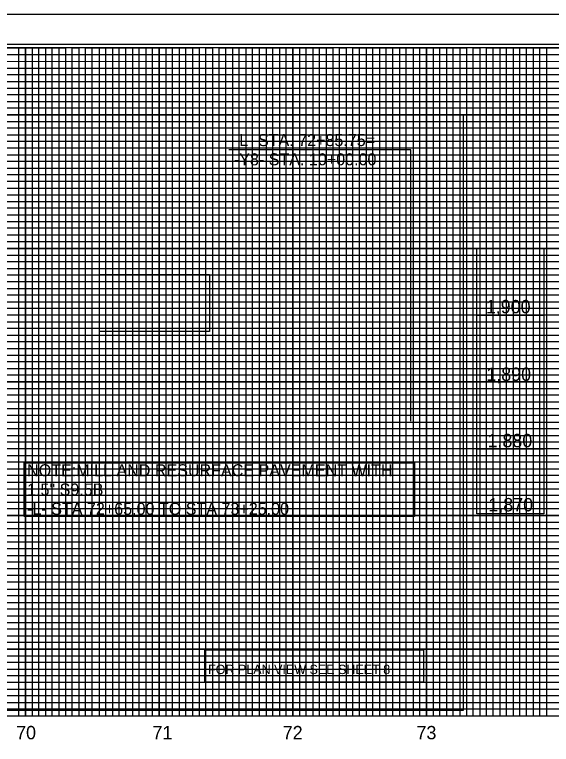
# Model space of a CAD drawing. Extents: x 557032 to 558840, y 515971 to 517218.
# Drawn here: x 557641 to 558043, y 516672 to 517218 of the extents above; entities that cross this region are included whole.
import ezdxf

# ---------------------------------------------------------------- set-up
doc = ezdxf.new("R2010")
doc.units = 0
for name, color, linetype in [('Exist Vertical Profile Horizontal Axis Label Major', 7, 'Continuous'), ('Exist Vertical Profile Vertical Axis Label', 7, 'Continuous'), ('Prop Dimension', 7, 'Continuous'), ('Prop Vertical Profile Grade Label', 7, 'Continuous'), ('Prop VPI Label', 7, 'Continuous'), ('Scratch_Level_5', 7, 'Continuous'), ('Sheet Cutting Line CELL', 7, 'Continuous'), ('Sheet DOT Grid CELL', 7, 'Continuous'), ('Sheet Layout Profile Border Port 1', 7, 'Continuous'), ('Sheet Plot Border Inside CELL', 7, 'Continuous'), ('Sheet Plot Border Outside CELL', 7, 'Continuous'), ('Sheet Profile CELL', 7, 'Continuous'), ('Sheet Profile Grid Major CELL', 7, 'Continuous'), ('Sheet Profile Grid Middle CELL', 7, 'Continuous'), ('Sheet Profile Grid Minor CELL', 7, 'Continuous')]:
    doc.layers.add(name, color=color, linetype=linetype)

msp = doc.modelspace()

# ---------------------------------------------------------------- linework, layer by layer
at = {"layer": 'Prop Dimension'}
msp.add_lwpolyline([(557987.25, 517043.03), (558037.25, 517043.03), (558037.25, 516844.53), (557987.25, 516844.53)], close=True, dxfattribs=at)
at = {"layer": 'Prop Vertical Profile Grade Label'}
msp.add_lwpolyline([(557704.75, 517023.61), (557787.24, 517023.61), (557787.24, 516980.88), (557704.75, 516980.88)], close=True, dxfattribs=at)
at = {"layer": 'Prop VPI Label'}
for p, q in [((557937.8, 517116.93), (557801.7, 517116.93)), ((557937.8, 516913.82), (557937.8, 517116.93))]:
    msp.add_line(p, q, dxfattribs=at)
for points in [[(557648.49, 516883.17), (557940.55, 516883.17), (557940.55, 516842.35), (557648.49, 516842.35)], [(557648.9, 516882.67), (557939.86, 516882.67), (557939.86, 516842.66), (557648.9, 516842.66)], [(557783.58, 516742.65), (557947.28, 516742.65), (557947.28, 516718.54), (557783.58, 516718.54)], [(557783.58, 516742.65), (557947.28, 516742.65), (557947.28, 516718.54), (557783.58, 516718.54)]]:
    msp.add_lwpolyline(points, close=True, dxfattribs=at)
at = {"layer": 'Scratch_Level_5'}
msp.add_lwpolyline([(557249.45, 516896.35), (557249.45, 517017.65), (557251.99, 517143.31), (557976.89, 517143.33), (557976.9, 516697.32), (557249.46, 516697.3)], close=True, dxfattribs=at)
at = {"layer": 'Sheet Cutting Line CELL'}
msp.add_line((558716.45, 517218.17), (557032.45, 517218.17), dxfattribs=at)
at = {"layer": 'Sheet DOT Grid CELL'}
for p, q in [((557649.45, 516693.17), (557649.45, 517193.17)), ((557699.45, 516693.17), (557699.45, 517193.17)), ((557749.45, 516693.17), (557749.45, 517193.17)), ((557799.45, 516693.17), (557799.45, 517193.17)), ((557849.45, 516693.17), (557849.45, 517193.17)), ((557899.45, 516693.17), (557899.45, 517193.17)), ((557949.45, 516693.17), (557949.45, 517193.17)), ((557999.45, 516693.17), (557999.45, 517193.17)), ((558499.4, 517143.17), (557199.45, 517143.17)), ((558499.4, 517093.17), (557199.45, 517093.17)), ((558499.45, 517043.17), (557199.45, 517043.17)), ((558699.45, 516993.17), (557199.45, 516993.17)), ((558699.45, 516943.17), (557199.45, 516943.17)), ((558699.45, 516893.17), (557199.45, 516893.17)), ((558699.45, 516843.17), (557199.45, 516843.17)), ((558699.45, 516793.17), (557199.45, 516793.17)), ((558699.45, 516743.17), (557199.45, 516743.17))]:
    msp.add_line(p, q, dxfattribs=at)
at = {"layer": 'Sheet Layout Profile Border Port 1'}
msp.add_lwpolyline([(557249.45, 517032.12), (557249.45, 516693.17), (558649.45, 516693.17), (558649.45, 517032.12)], dxfattribs=at)
at = {"layer": 'Sheet Plot Border Inside CELL'}
msp.add_lwpolyline([(557045.45, 516140.62), (558711.95, 516140.62), (558711.95, 517195.72), (557045.45, 517195.72)], close=True, dxfattribs=at)
at = {"layer": 'Sheet Plot Border Outside CELL'}
msp.add_lwpolyline([(557032.45, 516118.17), (558716.45, 516118.17), (558716.45, 517218.17), (557032.45, 517218.17)], close=True, dxfattribs=at)
at = {"layer": 'Sheet Profile CELL'}
msp.add_line((557199.45, 516693.17), (558699.45, 516693.17), dxfattribs=at)
msp.add_lwpolyline([(558699.45, 517193.17), (557199.45, 517193.17), (557199.45, 516143.17), (558699.45, 516143.17)], close=True, dxfattribs=at)
at = {"layer": 'Sheet Profile Grid Major CELL'}
for p, q in [((557949.45, 517043.17), (557949.45, 516844.8)), ((557999.45, 516993.17), (557924.45, 516993.17)), ((557987.25, 516993.17), (558037.25, 516993.17)), ((557999.45, 516943.17), (557924.45, 516943.17)), ((557987.25, 516943.17), (558037.25, 516943.17)), ((557999.45, 516893.17), (557924.45, 516893.17)), ((557987.25, 516893.17), (558037.25, 516893.17))]:
    msp.add_line(p, q, dxfattribs=at)
for points in [[(557599.45, 517193.17), (557649.45, 517193.17), (557649.45, 516693.17), (557699.45, 516693.17), (557699.45, 517193.17), (557749.45, 517193.17), (557749.45, 516693.17), (557799.45, 516693.17), (557799.45, 517193.17), (557849.45, 517193.17), (557849.45, 516693.17), (557899.45, 516693.17), (557899.45, 517193.17), (557949.45, 517193.17), (557949.45, 516693.17), (557999.45, 516693.17), (557999.45, 517193.17), (558049.45, 517193.17)], [(557199.45, 517143.17), (558499.45, 517143.17)], [(558499.45, 517093.17), (557199.45, 517093.17), (557199.45, 517043.17), (558499.45, 517043.17)], [(558699.45, 516993.17), (557199.45, 516993.17), (557199.45, 516943.17), (558699.45, 516943.17)], [(558699.45, 516893.17), (557199.45, 516893.17), (557199.45, 516843.17), (558699.45, 516843.17)], [(558699.45, 516793.17), (557199.45, 516793.17), (557199.45, 516793.17), (557199.45, 516743.17), (558699.45, 516743.17)]]:
    msp.add_lwpolyline(points, dxfattribs=at)
at = {"layer": 'Sheet Profile Grid Middle CELL'}
msp.add_line((557199.45, 517168.17), (558499.4, 517168.17), dxfattribs=at)
for points in [[(557624.45, 517193.17), (557674.45, 517193.17), (557674.45, 516693.17), (557724.45, 516693.17), (557724.45, 517193.17), (557774.45, 517193.17), (557774.45, 516693.17), (557824.45, 516693.17), (557824.45, 516693.17), (557824.45, 517193.17), (557874.45, 517193.17), (557874.45, 516693.17), (557924.45, 516693.17), (557924.45, 517193.17), (557974.45, 517193.17), (557974.45, 516693.17), (558024.45, 516693.17), (558024.45, 517193.17), (558074.45, 517193.17)], [(558499.45, 517118.17), (557199.45, 517118.17), (557199.45, 517068.17), (558499.45, 517068.17)], [(558699.45, 517018.17), (557199.45, 517018.17), (557199.45, 516968.17), (558524.45, 516968.17)], [(558699.45, 516918.17), (557199.45, 516918.17), (557199.45, 516868.17), (558699.45, 516868.17)], [(558699.45, 516818.17), (557199.45, 516818.17), (557199.45, 516768.17), (558699.45, 516768.17)], [(558699.45, 516718.17), (557199.45, 516718.17)]]:
    msp.add_lwpolyline(points, dxfattribs=at)
at = {"layer": 'Sheet Profile Grid Minor CELL'}
for p, q in [((557249.45, 517188.17), (558499.45, 517188.17)), ((558499.45, 517183.17), (557249.45, 517182.82)), ((557249.45, 517178.17), (558499.45, 517178.17)), ((558499.4, 517058.17), (557249.45, 517058.17)), ((558499.45, 517053.17), (557249.45, 517053.17)), ((558499.45, 517048.17), (557249.45, 517048.17)), ((557249.45, 517038.17), (558499.45, 517038.17)), ((558499.45, 517033.17), (557249.45, 517033.17)), ((557249.45, 517028.17), (558649.45, 517028.17)), ((558649.45, 517008.17), (557249.45, 517008.17)), ((557249.45, 517003.17), (558649.45, 517003.17)), ((558649.45, 516983.17), (557249.45, 516983.17)), ((557249.45, 516978.17), (558649.45, 516978.17)), ((558649.45, 516958.17), (557249.45, 516958.17)), ((557249.45, 516953.17), (558649.45, 516953.17)), ((558649.45, 516948.17), (557249.45, 516948.17)), ((557249.45, 516938.17), (558649.45, 516938.17)), ((558649.45, 516933.17), (557249.45, 516933.17)), ((557249.45, 516928.17), (558649.45, 516928.17)), ((558649.45, 516923.17), (557249.45, 516923.17)), ((557249.45, 516913.17), (558649.45, 516913.17)), ((558649.45, 516908.17), (557249.45, 516908.17)), ((557249.45, 516903.17), (558649.45, 516903.17)), ((558649.45, 516898.17), (557249.45, 516898.17)), ((557249.45, 516888.17), (558649.45, 516888.17)), ((558649.45, 516883.17), (557249.45, 516883.17)), ((557249.45, 516878.17), (558649.45, 516878.17)), ((558649.45, 516873.17), (557249.45, 516873.17)), ((557249.45, 516863.17), (558649.45, 516863.17)), ((558649.45, 516858.17), (557249.45, 516858.17)), ((557249.45, 516853.17), (558649.45, 516853.17)), ((558649.45, 516848.17), (557249.45, 516848.17)), ((557249.45, 516838.17), (558649.45, 516838.17)), ((558649.45, 516833.17), (557249.45, 516833.17)), ((557249.45, 516828.17), (558649.45, 516828.17)), ((558649.45, 516823.17), (557249.45, 516823.17)), ((557249.45, 516813.17), (558649.45, 516813.17)), ((558649.45, 516808.17), (557249.45, 516808.17)), ((558649.45, 516803.17), (557249.45, 516803.17)), ((558649.45, 516798.17), (557249.45, 516798.17)), ((557249.45, 516788.17), (558649.45, 516788.17)), ((558649.45, 516783.17), (557249.45, 516783.17)), ((557249.45, 516778.17), (558649.45, 516778.17)), ((558649.45, 516773.17), (557249.45, 516773.17)), ((557249.45, 516763.17), (558649.45, 516763.17)), ((558649.45, 516758.17), (557249.45, 516758.17)), ((557249.45, 516753.17), (558649.45, 516753.17)), ((558649.45, 516748.17), (557249.45, 516748.17)), ((557249.45, 516738.17), (558649.45, 516738.17)), ((558649.45, 516733.17), (557249.45, 516733.17)), ((557249.45, 516728.17), (558649.45, 516728.17)), ((558649.45, 516723.17), (557249.45, 516723.17)), ((557249.45, 516713.17), (558649.45, 516713.17)), ((558649.45, 516708.17), (557249.45, 516708.17)), ((557249.45, 516703.17), (558649.45, 516703.17))]:
    msp.add_line(p, q, dxfattribs=at)
for points in [[(557639.45, 516693.17), (557644.45, 516693.17), (557644.45, 517193.17), (557654.45, 517193.17), (557654.45, 516693.17), (557659.45, 516693.17), (557659.45, 517193.17), (557664.45, 517193.17), (557664.45, 516693.17), (557669.45, 516693.17), (557669.45, 517193.17), (557679.45, 517193.17), (557679.45, 516693.17), (557684.45, 516693.17), (557684.45, 517193.17), (557689.45, 517193.17), (557689.45, 516693.17), (557694.45, 516693.17), (557694.45, 517193.17), (557704.45, 517193.17), (557704.45, 516693.17), (557709.45, 516693.17), (557709.45, 517193.17), (557714.45, 517193.17), (557714.45, 516693.17), (557719.45, 516693.17), (557719.45, 517193.17), (557729.45, 517193.17), (557729.45, 516693.17), (557734.45, 516693.17), (557734.45, 517193.17), (557739.45, 517193.17), (557739.45, 516693.17), (557744.45, 516693.17), (557744.45, 517193.17), (557754.45, 517193.17), (557754.45, 516693.17), (557759.45, 516693.17), (557759.45, 517193.17), (557764.45, 517193.17), (557764.45, 516693.17), (557769.45, 516693.17), (557769.45, 517193.17), (557779.45, 517193.17)], [(557779.45, 517193.17), (557779.45, 516693.17), (557784.45, 516693.17), (557784.45, 517193.17), (557789.45, 517193.17), (557789.45, 516693.17), (557794.45, 516693.17), (557794.45, 517193.17), (557804.45, 517193.17), (557804.45, 516693.17), (557809.45, 516693.17), (557809.45, 517193.17), (557814.45, 517193.17), (557814.45, 516693.17), (557819.45, 516693.17), (557819.45, 517193.17), (557829.45, 517193.17), (557829.45, 516693.17), (557834.45, 516693.17), (557834.45, 517193.17), (557839.45, 517193.17), (557839.45, 516693.17), (557844.45, 516693.17), (557844.45, 517193.17), (557854.45, 517193.17), (557854.45, 516693.17), (557859.45, 516693.17), (557859.45, 517193.17), (557864.45, 517193.17), (557864.45, 516693.17), (557869.45, 516693.17), (557869.45, 517193.17), (557879.45, 517193.17), (557879.45, 516693.17), (557884.45, 516693.17), (557884.45, 517193.17), (557889.45, 517193.17), (557889.45, 516693.17), (557894.45, 516693.17), (557894.45, 517193.17), (557904.45, 517193.17), (557904.45, 516693.17), (557904.45, 516693.17), (557909.45, 516693.17), (557909.45, 517193.17), (557914.45, 517193.17), (557914.45, 516693.17), (557919.45, 516693.17), (557919.45, 517193.17), (557929.45, 517193.17), (557929.45, 516693.17), (557934.45, 516693.17), (557934.45, 517193.17), (557939.45, 517193.17), (557939.45, 516693.17), (557944.45, 516693.17), (557944.45, 517193.17), (557954.45, 517193.17), (557954.45, 516693.17), (557959.45, 516693.17), (557959.45, 517193.17), (557964.45, 517193.17), (557964.45, 516693.17), (557969.45, 516693.17), (557969.45, 517193.17), (557979.45, 517193.17), (557979.45, 516693.17), (557984.45, 516693.17), (557984.45, 517193.17), (557989.45, 517193.17), (557989.45, 516693.17), (557994.45, 516693.17), (557994.45, 517193.17), (558004.45, 517193.17), (558004.45, 516693.17), (558009.45, 516693.17), (558009.45, 517193.17), (558014.45, 517193.17), (558014.45, 516693.17), (558019.45, 516693.17), (558019.45, 517193.17), (558029.45, 517193.17), (558029.45, 516693.17), (558034.45, 516693.17), (558034.45, 517193.17), (558039.45, 517193.17), (558039.45, 516693.17), (558044.45, 516693.17)], [(558499.45, 517173.17), (557249.45, 517173.17), (557249.45, 517163.17), (558499.45, 517163.17)], [(558499.4, 517158.17), (557249.45, 517158.17), (557249.45, 517153.17), (558499.45, 517153.17)], [(558499.45, 517148.17), (557249.45, 517148.17), (557249.45, 517138.17), (558499.45, 517138.17)], [(558499.45, 517133.17), (557249.45, 517133.17), (557249.45, 517128.17), (558499.45, 517128.17)], [(558499.45, 517123.17), (557249.45, 517123.17), (557249.45, 517113.17), (558499.45, 517113.17)], [(558499.45, 517108.17), (557249.45, 517108.17), (557249.45, 517103.17), (558499.45, 517103.17)], [(558499.45, 517098.17), (557249.45, 517098.17), (557249.45, 517088.17), (558499.45, 517088.17)], [(558499.45, 517083.07), (557249.55, 517083.07), (557249.55, 517078.17), (558499.45, 517078.17)], [(558499.45, 517073.17), (557249.45, 517073.17), (557249.45, 517063.17), (558499.45, 517063.17)], [(558649.45, 517023.17), (557249.45, 517023.17), (557249.45, 517013.17), (558649.45, 517013.17)], [(558649.45, 516998.17), (557249.45, 516998.17), (557249.45, 516988.17), (558649.45, 516988.17)], [(558649.45, 516973.17), (557249.45, 516973.17), (557249.45, 516963.17), (558649.45, 516963.17)], [(558649.45, 516698.17), (557249.45, 516698.17)]]:
    msp.add_lwpolyline(points, dxfattribs=at)

# ---------------------------------------------------------------- texts
at = {"layer": 'Exist Vertical Profile Horizontal Axis Label Major'}
for s, p in [('70', (557642.43, 516675.67)), ('71', (557744.49, 516675.67)), ('72', (557841.99, 516675.67)), ('73', (557942.07, 516675.67))]:
    msp.add_text(s, height=10, dxfattribs=at).set_placement(p)
at = {"layer": 'Exist Vertical Profile Vertical Axis Label'}
for s, p in [('1,900', (557993.97, 516994.55)), ('1,890', (557994.34, 516943.93)), ('1,880', (557995.21, 516894.3)), ('1,870', (557995.83, 516846.29))]:
    msp.add_text(s, height=10, dxfattribs=at).set_placement(p)
at = {"layer": 'Prop VPI Label'}
for s, height, p in [('-L- STA. 72+85.75=', 9, (557805.38, 517119.73)), ('-Y8- STA. 10+00.00', 9, (557805.38, 517105.33)), ('NOTE:MILL AND RESURFACE PAVEMENT WITH', 9, (557650.64, 516872.55)), ('1.5" S9.5B', 9, (557650.64, 516858.15)), ('-L- STA 72+65.00 TO STA 73+25.00', 9, (557650.64, 516843.75)), ('FOR PLAN VIEW SEE SHEET 8', 7, (557786.09, 516724.49))]:
    msp.add_text(s, height=height, dxfattribs=at).set_placement(p)

doc.saveas('drawing.dxf')
